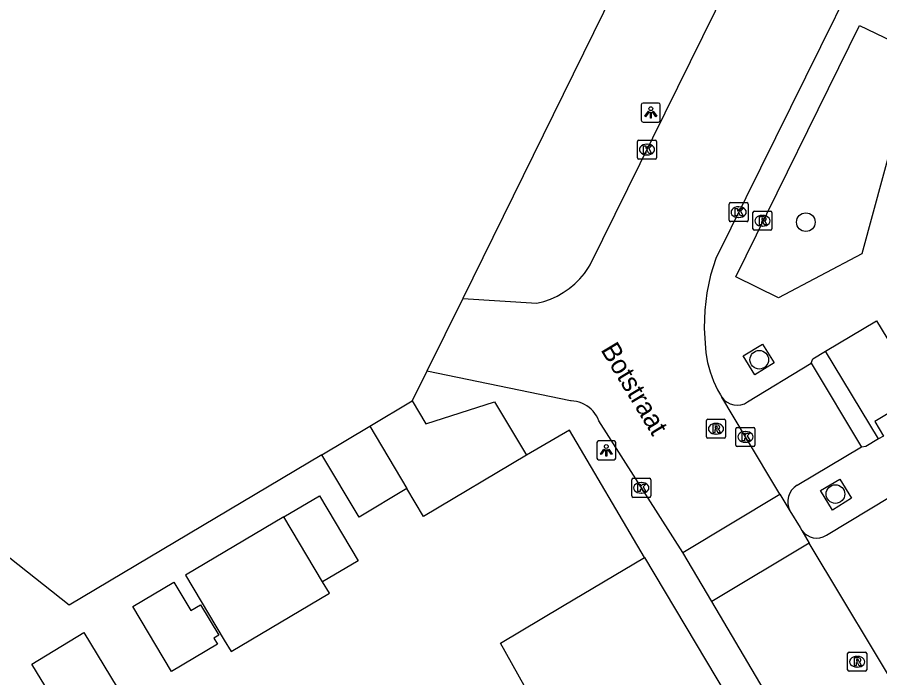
# Model space of a CAD drawing. Extents: x 159222 to 160346, y 381249 to 382166.
# Drawn here: x 160195.33 to 160240.6, y 382021.73 to 382056.42 of the extents above; entities that cross this region are included whole.
import ezdxf

# ---------------------------------------------------------------- set-up
doc = ezdxf.new("R2010")
doc.units = 0
for name, color, linetype in [('IMGEO_Boom', 7, 'Continuous'), ('IMGEO_Haag', 7, 'Continuous'), ('IMGEO_Kolk', 7, 'Continuous'), ('IMGEO_Lichtpunt', 7, 'Continuous'), ('IMGEO_Muur', 7, 'Continuous'), ('IMGEO_Openbare_ruimte_label', 7, 'Continuous'), ('IMGEO_Pand', 7, 'Continuous'), ('IMGEO_Parkeervlak_open', 7, 'Continuous'), ('IMGEO_Rijbaan_lokaal_open', 7, 'Continuous'), ('IMGEO_Rioolput', 7, 'Continuous'), ('IMGEO_Voetpad_open', 7, 'Continuous')]:
    doc.layers.add(name, color=color, linetype=linetype)

msp = doc.modelspace()

# ---------------------------------------------------------------- linework, layer by layer
at = {"layer": 'IMGEO_Boom'}
for centre in [(160236.721, 382045.662), (160234.274, 382038.435), (160238.273, 382031.381)]:
    msp.add_circle(centre, 0.489, dxfattribs=at)
at = {"layer": 'IMGEO_Haag'}
msp.add_lwpolyline([(160240.533, 382034.275), (160237.755, 382038.878)], dxfattribs=at)
at = {"layer": 'IMGEO_Kolk'}
for p, q in [((160227.881, 382049.047), (160227.881, 382049.899)), ((160227.956, 382049.973), (160228.808, 382049.973)), ((160228.369, 382049.753), (160228.394, 382049.753)), ((160228.882, 382049.899), (160228.882, 382049.047)), ((160228.808, 382048.973), (160227.956, 382048.973)), ((160228.392, 382049.193), (160228.367, 382049.193)), ((160232.692, 382045.761), (160232.692, 382046.613)), ((160232.767, 382046.687), (160233.619, 382046.687)), ((160233.693, 382046.613), (160233.693, 382045.761)), ((160233.18, 382046.467), (160233.205, 382046.467)), ((160233.619, 382045.687), (160232.767, 382045.687)), ((160233.203, 382045.907), (160233.178, 382045.907)), ((160233.048, 382033.957), (160233.048, 382034.809)), ((160233.123, 382034.883), (160233.975, 382034.883)), ((160234.049, 382034.809), (160234.049, 382033.957)), ((160233.536, 382034.663), (160233.561, 382034.663)), ((160233.975, 382033.883), (160233.123, 382033.883)), ((160233.559, 382034.103), (160233.534, 382034.103)), ((160227.582, 382031.283), (160227.582, 382032.135)), ((160227.657, 382032.209), (160228.509, 382032.209)), ((160228.583, 382032.135), (160228.583, 382031.283)), ((160228.07, 382031.989), (160228.095, 382031.989)), ((160228.509, 382031.209), (160227.657, 382031.209)), ((160228.093, 382031.429), (160228.068, 382031.429))]:
    msp.add_line(p, q, dxfattribs=at)
for points in [[(160227.881, 382049.047), (160227.881, 382049.899)], [(160227.956, 382049.973), (160228.808, 382049.973)], [(160228.882, 382049.899), (160228.882, 382049.047)], [(160228.202, 382049.673), (160228.325, 382049.673), (160228.325, 382049.522), (160228.455, 382049.673), (160228.619, 382049.673), (160228.473, 382049.522), (160228.626, 382049.273), (160228.474, 382049.273), (160228.389, 382049.437), (160228.325, 382049.37), (160228.325, 382049.273), (160228.202, 382049.273), (160228.202, 382049.673)], [(160228.808, 382048.973), (160227.956, 382048.973)], [(160232.692, 382045.761), (160232.692, 382046.613)], [(160232.767, 382046.687), (160233.619, 382046.687)], [(160233.693, 382046.613), (160233.693, 382045.761)], [(160233.013, 382046.387), (160233.136, 382046.387), (160233.136, 382046.236), (160233.266, 382046.387), (160233.43, 382046.387), (160233.284, 382046.236), (160233.437, 382045.987), (160233.285, 382045.987), (160233.2, 382046.151), (160233.136, 382046.084), (160233.136, 382045.987), (160233.013, 382045.987), (160233.013, 382046.387)], [(160233.619, 382045.687), (160232.767, 382045.687)], [(160233.048, 382033.957), (160233.048, 382034.809)], [(160233.123, 382034.883), (160233.975, 382034.883)], [(160234.049, 382034.809), (160234.049, 382033.957)], [(160233.369, 382034.583), (160233.492, 382034.583), (160233.492, 382034.432), (160233.622, 382034.583), (160233.786, 382034.583), (160233.64, 382034.432), (160233.793, 382034.183), (160233.641, 382034.183), (160233.556, 382034.347), (160233.492, 382034.28), (160233.492, 382034.183), (160233.369, 382034.183), (160233.369, 382034.583)], [(160233.975, 382033.883), (160233.123, 382033.883)], [(160227.582, 382031.283), (160227.582, 382032.135)], [(160227.657, 382032.209), (160228.509, 382032.209)], [(160228.583, 382032.135), (160228.583, 382031.283)], [(160227.903, 382031.909), (160228.026, 382031.909), (160228.026, 382031.758), (160228.156, 382031.909), (160228.32, 382031.909), (160228.174, 382031.758), (160228.327, 382031.509), (160228.175, 382031.509), (160228.09, 382031.673), (160228.026, 382031.606), (160228.026, 382031.509), (160227.903, 382031.509), (160227.903, 382031.909)], [(160228.509, 382031.209), (160227.657, 382031.209)]]:
    msp.add_lwpolyline(points, dxfattribs=at)
for centre, start, end in [((160227.958, 382049.897), 91.552, 178.448), ((160227.958, 382049.897), 91.552, 178.448), ((160228.806, 382049.897), 1.552, 88.448), ((160228.806, 382049.897), 1.552, 88.448), ((160227.958, 382049.049), 181.552, 268.448), ((160227.958, 382049.049), 181.552, 268.448), ((160228.806, 382049.049), 271.552, 358.448), ((160228.806, 382049.049), 271.552, 358.448), ((160232.769, 382046.611), 91.552, 178.448), ((160232.769, 382046.611), 91.552, 178.448), ((160233.617, 382046.611), 1.552, 88.448), ((160233.617, 382046.611), 1.552, 88.448), ((160232.769, 382045.763), 181.552, 268.448), ((160232.769, 382045.763), 181.552, 268.448), ((160233.617, 382045.763), 271.552, 358.448), ((160233.617, 382045.763), 271.552, 358.448), ((160233.125, 382034.807), 91.552, 178.448), ((160233.125, 382034.807), 91.552, 178.448), ((160233.973, 382034.807), 1.552, 88.448), ((160233.973, 382034.807), 1.552, 88.448), ((160233.125, 382033.959), 181.552, 268.448), ((160233.125, 382033.959), 181.552, 268.448), ((160233.973, 382033.959), 271.552, 358.448), ((160233.973, 382033.959), 271.552, 358.448), ((160227.659, 382032.133), 91.552, 178.448), ((160227.659, 382032.133), 91.552, 178.448), ((160228.507, 382032.133), 1.552, 88.448), ((160228.507, 382032.133), 1.552, 88.448), ((160227.659, 382031.285), 181.552, 268.448), ((160227.659, 382031.285), 181.552, 268.448), ((160228.507, 382031.285), 271.552, 358.448), ((160228.507, 382031.285), 271.552, 358.448)]:
    msp.add_arc(centre, 0.0765, start, end, dxfattribs=at)
for centre, major_axis, ratio, start_param, end_param in [((160228.368, 382049.473), (-0.387, 0.002), 0.722429, 4.712389, 7.853982), ((160228.393, 382049.473), (-0.39, 0.002), 0.717154, 1.570796, 4.712389), ((160233.179, 382046.187), (-0.387, 0.002), 0.722429, 4.712389, 7.853982), ((160233.204, 382046.187), (-0.39, 0.002), 0.717154, 1.570796, 4.712389), ((160233.535, 382034.383), (-0.387, 0.002), 0.722429, 4.712389, 7.853982), ((160233.56, 382034.383), (-0.39, 0.002), 0.717154, 1.570796, 4.712389), ((160228.069, 382031.709), (-0.387, 0.002), 0.722429, 4.712389, 7.853982), ((160228.094, 382031.709), (-0.39, 0.002), 0.717154, 1.570796, 4.712389)]:
    msp.add_ellipse(centre, major_axis=major_axis, ratio=ratio, start_param=start_param, end_param=end_param, dxfattribs=at)
at = {"layer": 'IMGEO_Lichtpunt'}
for p, q in [((160228.082, 382051.822), (160228.082, 382051.015)), ((160228.082, 382051.822), (160228.082, 382051.015)), ((160228.984, 382051.917), (160228.176, 382051.917)), ((160228.984, 382051.917), (160228.176, 382051.917)), ((160229.078, 382051.015), (160229.078, 382051.822)), ((160229.078, 382051.015), (160229.078, 382051.822)), ((160228.176, 382050.921), (160228.984, 382050.921)), ((160228.176, 382050.921), (160228.984, 382050.921)), ((160225.748, 382034.081), (160225.748, 382033.274)), ((160225.748, 382034.081), (160225.748, 382033.274)), ((160226.65, 382034.176), (160225.842, 382034.176)), ((160226.65, 382034.176), (160225.842, 382034.176)), ((160226.744, 382033.274), (160226.744, 382034.081)), ((160226.744, 382033.274), (160226.744, 382034.081)), ((160225.842, 382033.18), (160226.65, 382033.18)), ((160225.842, 382033.18), (160226.65, 382033.18))]:
    msp.add_line(p, q, dxfattribs=at)
for points in [[(160228.456, 382051.486), (160228.495, 382051.458), (160228.307, 382051.196), (160228.269, 382051.223), (160228.456, 382051.486)], [(160228.558, 382051.438), (160228.605, 382051.438), (160228.605, 382051.116), (160228.558, 382051.116), (160228.558, 382051.438)], [(160228.668, 382051.458), (160228.706, 382051.485), (160228.893, 382051.223), (160228.854, 382051.195), (160228.668, 382051.458)], [(160226.122, 382033.745), (160226.161, 382033.717), (160225.973, 382033.455), (160225.935, 382033.482), (160226.122, 382033.745)], [(160226.224, 382033.697), (160226.271, 382033.697), (160226.271, 382033.375), (160226.224, 382033.375), (160226.224, 382033.697)], [(160226.334, 382033.717), (160226.372, 382033.744), (160226.559, 382033.482), (160226.52, 382033.454), (160226.334, 382033.717)]]:
    msp.add_lwpolyline(points, dxfattribs=at)
for centre in [(160228.581, 382051.62), (160226.247, 382033.879)]:
    msp.add_circle(centre, 0.0994, dxfattribs=at)
for centre, start, end in [((160228.176, 382051.822), 90, 180), ((160228.176, 382051.822), 90, 180), ((160228.984, 382051.822), 0, 90), ((160228.984, 382051.822), 0, 90), ((160228.176, 382051.015), 180, 270), ((160228.176, 382051.015), 180, 270), ((160228.984, 382051.015), 270, 0), ((160228.984, 382051.015), 270, 360), ((160225.842, 382034.081), 90, 180), ((160225.842, 382034.081), 90, 180), ((160226.65, 382034.081), 0, 90), ((160226.65, 382034.081), 0, 90), ((160225.842, 382033.274), 180, 270), ((160225.842, 382033.274), 180, 270), ((160226.65, 382033.274), 270, 0), ((160226.65, 382033.274), 270, 360)]:
    msp.add_arc(centre, 0.0946, start, end, dxfattribs=at)
at = {"layer": 'IMGEO_Muur'}
msp.add_lwpolyline([(160228.248, 382028.054), (160224.316, 382034.737), (160222.049, 382033.417)], dxfattribs=at)
at = {"layer": 'IMGEO_Pand'}
for points in [[(160234.915, 382070.865), (160228.115, 382057.032), (160226.628, 382057.764), (160218.71, 382041.658)], [(160211.313, 382033.447), (160198.054, 382025.542), (160173.539, 382044.963), (160179.55, 382055.171), (160182.923, 382060.898)], [(160218.71, 382041.658), (160216.828, 382037.83)], [(160216.828, 382037.83), (160216.062, 382036.272)], [(160213.829, 382034.944), (160216.062, 382036.272)], [(160216.062, 382036.272), (160216.778, 382035.071), (160220.373, 382036.229), (160222.049, 382033.417)], [(160211.313, 382033.447), (160213.829, 382034.944)], [(160213.829, 382034.944), (160215.778, 382031.668)], [(160215.778, 382031.668), (160213.266, 382030.171), (160211.313, 382033.447)], [(160222.049, 382033.417), (160216.653, 382030.201), (160215.778, 382031.668)], [(160209.328, 382030.178), (160211.198, 382031.286), (160213.218, 382027.876), (160211.356, 382026.773)], [(160209.328, 382030.178), (160204.166, 382027.119), (160206.194, 382023.714), (160206.548, 382023.12), (160211.71, 382026.179), (160211.356, 382026.773)], [(160211.356, 382026.773), (160209.328, 382030.178)], [(160221.931, 382021.33), (160220.691, 382023.549), (160223.954, 382025.494), (160228.248, 382028.054)], [(160228.248, 382028.054), (160233.082, 382019.946)], [(160201.395, 382025.477), (160203.544, 382026.75), (160204.434, 382025.258), (160204.948, 382025.565), (160205.903, 382023.963), (160205.646, 382023.81), (160205.835, 382023.501), (160203.415, 382022.067), (160201.395, 382025.477)], [(160196.087, 382022.455), (160198.814, 382024.117), (160200.925, 382020.653), (160198.198, 382018.992), (160196.087, 382022.455)]]:
    msp.add_lwpolyline(points, dxfattribs=at)
at = {"layer": 'IMGEO_Parkeervlak_open'}
msp.add_lwpolyline([(160237.005, 382038.25), (160239.639, 382033.848)], dxfattribs=at)
at = {"layer": 'IMGEO_Rijbaan_lokaal_open'}
for points in [[(160246.603, 382073.202), (160246.042, 382072.193), (160244.545, 382069.152), (160231.992, 382043.761), (160231.719, 382042.87), (160231.528, 382041.958), (160231.418, 382041.032), (160231.391, 382040.1), (160231.434, 382039.313), (160231.475, 382038.801), (160231.563, 382038.294), (160231.695, 382037.798), (160231.87, 382037.315), (160232.089, 382036.849), (160232.237, 382036.584), (160232.307, 382036.466)], [(160218.71, 382041.658), (160222.601, 382041.406), (160222.965, 382041.497), (160223.32, 382041.621), (160223.662, 382041.776), (160223.988, 382041.961), (160224.297, 382042.174), (160224.586, 382042.414), (160224.852, 382042.678), (160225.094, 382042.966), (160225.309, 382043.274), (160225.401, 382043.427), (160237.898, 382068.773)], [(160230.268, 382028.307), (160225.856, 382035.228), (160225.798, 382035.362), (160225.727, 382035.49), (160225.646, 382035.612), (160225.554, 382035.726), (160225.452, 382035.831), (160225.342, 382035.926), (160225.223, 382036.012), (160225.097, 382036.086), (160224.965, 382036.149), (160224.828, 382036.2), (160224.687, 382036.238), (160224.543, 382036.264), (160224.397, 382036.276), (160224.375, 382036.277), (160216.828, 382037.83)], [(160235.356, 382031.372), (160233.548, 382034.382), (160232.307, 382036.466)], [(160230.268, 382028.307), (160235.356, 382031.372)], [(160235.356, 382031.372), (160235.887, 382030.501)], [(160235.887, 382030.501), (160236.42, 382029.627), (160236.517, 382029.462)], [(160236.517, 382029.462), (160236.902, 382028.808)], [(160236.902, 382028.808), (160231.787, 382025.73)], [(160242.637, 382019.252), (160241.991, 382020.325), (160236.902, 382028.808)], [(160231.787, 382025.73), (160230.268, 382028.307)], [(160236.001, 382018.386), (160234.942, 382020.406), (160231.787, 382025.73)]]:
    msp.add_lwpolyline(points, dxfattribs=at)
at = {"layer": 'IMGEO_Rioolput'}
for p, q in [((160233.941, 382045.308), (160233.941, 382046.16)), ((160234.016, 382046.234), (160234.868, 382046.234)), ((160234.942, 382046.16), (160234.942, 382045.308)), ((160234.429, 382046.014), (160234.454, 382046.014)), ((160234.868, 382045.234), (160234.016, 382045.234)), ((160234.452, 382045.454), (160234.427, 382045.454)), ((160231.503, 382034.384), (160231.503, 382035.236)), ((160231.578, 382035.31), (160232.43, 382035.31)), ((160232.504, 382035.236), (160232.504, 382034.384)), ((160231.991, 382035.09), (160232.016, 382035.09)), ((160232.014, 382034.53), (160231.989, 382034.53)), ((160232.43, 382034.31), (160231.578, 382034.31)), ((160238.988, 382023.076), (160239.84, 382023.076)), ((160238.913, 382022.15), (160238.913, 382023.002)), ((160239.401, 382022.856), (160239.426, 382022.856)), ((160239.914, 382023.002), (160239.914, 382022.15)), ((160239.424, 382022.296), (160239.399, 382022.296)), ((160239.84, 382022.076), (160238.988, 382022.076))]:
    msp.add_line(p, q, dxfattribs=at)
for points in [[(160233.941, 382045.308), (160233.941, 382046.16)], [(160234.016, 382046.234), (160234.868, 382046.234)], [(160234.942, 382046.16), (160234.942, 382045.308)], [(160234.53, 382045.932), (160234.278, 382045.934), (160234.278, 382045.534)], [(160234.278, 382045.534), (160234.402, 382045.534), (160234.402, 382045.696), (160234.413, 382045.696)], [(160234.456, 382045.853), (160234.402, 382045.853), (160234.402, 382045.772)], [(160234.402, 382045.772), (160234.454, 382045.772)], [(160234.46, 382045.667), (160234.531, 382045.534), (160234.671, 382045.534), (160234.606, 382045.66)], [(160234.868, 382045.234), (160234.016, 382045.234)], [(160231.503, 382034.384), (160231.503, 382035.236)], [(160231.578, 382035.31), (160232.43, 382035.31)], [(160232.504, 382035.236), (160232.504, 382034.384)], [(160232.092, 382035.008), (160231.84, 382035.01), (160231.84, 382034.61)], [(160232.018, 382034.929), (160231.964, 382034.929), (160231.964, 382034.848)], [(160231.964, 382034.848), (160232.016, 382034.848)], [(160231.84, 382034.61), (160231.964, 382034.61), (160231.964, 382034.772), (160231.975, 382034.772)], [(160232.022, 382034.743), (160232.093, 382034.61), (160232.233, 382034.61), (160232.168, 382034.736)], [(160232.43, 382034.31), (160231.578, 382034.31)], [(160238.988, 382023.076), (160239.84, 382023.076)], [(160238.913, 382022.15), (160238.913, 382023.002)], [(160239.502, 382022.774), (160239.25, 382022.776), (160239.25, 382022.376)], [(160239.428, 382022.695), (160239.374, 382022.695), (160239.374, 382022.614)], [(160239.374, 382022.614), (160239.426, 382022.614)], [(160239.914, 382023.002), (160239.914, 382022.15)], [(160239.25, 382022.376), (160239.374, 382022.376), (160239.374, 382022.538), (160239.385, 382022.538)], [(160239.432, 382022.509), (160239.503, 382022.376), (160239.643, 382022.376), (160239.578, 382022.502)], [(160239.84, 382022.076), (160238.988, 382022.076)]]:
    msp.add_lwpolyline(points, dxfattribs=at)
for centre, radius, start, end in [((160234.018, 382046.158), 0.0765, 91.552, 178.448), ((160234.018, 382046.158), 0.0765, 91.552, 178.448), ((160234.866, 382046.158), 0.0765, 1.552, 88.448), ((160234.866, 382046.158), 0.0765, 1.552, 88.448), ((160234.412, 382045.643), 0.0533, 26.0293, 88.6989), ((160234.438, 382045.961), 0.19, 274.7715, 282.9687), ((160234.462, 382045.757), 0.0964, 77.0061, 93.1865), ((160234.476, 382045.814), 0.0378, 276.6634, 79.6772), ((160234.529, 382045.822), 0.109, 350.3612, 89.416), ((160234.527, 382045.822), 0.112, 277.5842, 350.9817), ((160234.511, 382045.607), 0.108, 29.5134, 73.7905), ((160234.018, 382045.31), 0.0765, 181.552, 268.448), ((160234.018, 382045.31), 0.0765, 181.552, 268.448), ((160234.866, 382045.31), 0.0765, 271.552, 358.448), ((160234.866, 382045.31), 0.0765, 271.552, 358.448), ((160231.58, 382035.234), 0.0765, 91.552, 178.448), ((160231.58, 382035.234), 0.0765, 91.552, 178.448), ((160232.428, 382035.234), 0.0765, 1.552, 88.448), ((160232.428, 382035.234), 0.0765, 1.552, 88.448), ((160232, 382035.037), 0.19, 274.7715, 282.9687), ((160232.024, 382034.833), 0.0964, 77.0061, 93.1865), ((160232.038, 382034.89), 0.0378, 276.6634, 79.6772), ((160232.091, 382034.898), 0.109, 350.3612, 89.416), ((160232.089, 382034.898), 0.112, 277.5842, 350.9817), ((160232.073, 382034.683), 0.108, 29.5134, 73.7905), ((160231.58, 382034.386), 0.0765, 181.552, 268.448), ((160231.58, 382034.386), 0.0765, 181.552, 268.448), ((160231.974, 382034.719), 0.0533, 26.0293, 88.6989), ((160232.428, 382034.386), 0.0765, 271.552, 358.448), ((160232.428, 382034.386), 0.0765, 271.552, 358.448), ((160238.99, 382023), 0.0765, 91.552, 178.448), ((160238.99, 382023), 0.0765, 91.552, 178.448), ((160239.838, 382023), 0.0765, 1.552, 88.448), ((160239.838, 382023), 0.0765, 1.552, 88.448), ((160239.41, 382022.803), 0.19, 274.7715, 282.9687), ((160239.434, 382022.599), 0.0964, 77.0061, 93.1865), ((160239.448, 382022.656), 0.0378, 276.6634, 79.6772), ((160239.501, 382022.664), 0.109, 350.3612, 89.416), ((160239.499, 382022.664), 0.112, 277.5842, 350.9817), ((160239.483, 382022.449), 0.108, 29.5134, 73.7905), ((160238.99, 382022.152), 0.0765, 181.552, 268.448), ((160238.99, 382022.152), 0.0765, 181.552, 268.448), ((160239.384, 382022.485), 0.0533, 26.0293, 88.6989), ((160239.838, 382022.152), 0.0765, 271.552, 358.448), ((160239.838, 382022.152), 0.0765, 271.552, 358.448)]:
    msp.add_arc(centre, radius, start, end, dxfattribs=at)
for centre, major_axis, ratio, start_param, end_param in [((160234.428, 382045.734), (-0.387, 0.002), 0.722429, 4.712389, 7.853982), ((160234.453, 382045.734), (-0.39, 0.002), 0.717154, 1.570796, 4.712389), ((160231.99, 382034.81), (-0.387, 0.002), 0.722429, 4.712389, 7.853982), ((160232.015, 382034.81), (-0.39, 0.002), 0.717154, 1.570796, 4.712389), ((160239.4, 382022.576), (-0.387, 0.002), 0.722429, 4.712389, 7.853982), ((160239.425, 382022.576), (-0.39, 0.002), 0.717154, 1.570796, 4.712389)]:
    msp.add_ellipse(centre, major_axis=major_axis, ratio=ratio, start_param=start_param, end_param=end_param, dxfattribs=at)
at = {"layer": 'IMGEO_Voetpad_open'}
for points in [[(160239.652, 382044.006), (160235.28, 382041.684), (160233.038, 382042.792), (160239.539, 382055.992), (160242.533, 382054.554), (160239.652, 382044.006)], [(160237.755, 382038.878), (160240.423, 382040.483), (160242.753, 382036.645), (160240.345, 382035.196), (160240.789, 382034.429), (160240.533, 382034.275)], [(160234.049, 382037.646), (160233.434, 382038.647), (160234.451, 382039.259), (160235.063, 382038.277), (160234.049, 382037.646)], [(160237.005, 382038.25), (160237.093, 382038.48), (160237.755, 382038.878)], [(160233.664, 382036.222), (160237.003, 382038.253), (160237.005, 382038.25)], [(160228.248, 382028.054), (160224.316, 382034.737), (160222.049, 382033.417)], [(160240.533, 382034.275), (160239.868, 382033.874), (160239.639, 382033.848)], [(160239.639, 382033.848), (160236.269, 382031.839)], [(160239.111, 382031.163), (160238.114, 382030.541), (160237.488, 382031.575), (160238.508, 382032.159), (160239.111, 382031.163)], [(160237.799, 382029.222), (160241.196, 382031.27)]]:
    msp.add_lwpolyline(points, dxfattribs=at)
for centre, radius, start, end in [((160233.108, 382037.026), 0.977, 214.9534, 304.66), ((160236.755, 382030.977), 0.99, 119.3944, 208.7374), ((160237.287, 382030.031), 0.958, 216.4783, 302.3147)]:
    msp.add_arc(centre, radius, start, end, dxfattribs=at)

# ---------------------------------------------------------------- texts
at = {"layer": 'IMGEO_Openbare_ruimte_label'}
msp.add_text('Botstraat', height=1, rotation=301.0522, dxfattribs=at).set_placement((160225.926, 382038.96))

doc.saveas('drawing.dxf')
